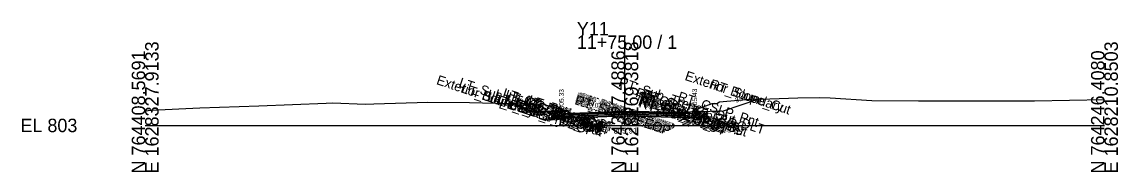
# Model space of a CAD drawing. Extents: x -26 to 203, y -10 to 6017.
# Drawn here: x -25.7 to 202.8, y 3490.3 to 3521.5 of the extents above; entities that cross this region are included whole.
import ezdxf

# ---------------------------------------------------------------- set-up
doc = ezdxf.new("R2010")
doc.units = 0
for name, color, linetype in [('Default', 7, 'Continuous'), ('Exist Cross Section Cell', 7, 'Continuous'), ('Exist XS Center Line Elevation Label', 7, 'Continuous'), ('Exist XS Ground Line', 7, 'Continuous'), ('Prop CMT Conc Surface', 7, 'Continuous'), ('Prop CMT Concrete Structures', 7, 'Continuous'), ('Prop CMT Pvmt Course 1', 7, 'Continuous'), ('Prop CMT Pvmt Course 1 CG', 7, 'Continuous'), ('Prop CMT Pvmt Course 2', 7, 'Continuous'), ('Prop CMT Pvmt Course 3', 7, 'Continuous'), ('Prop CMT Pvmt Surface', 7, 'Continuous'), ('Prop CMT Pvmt Wedge Surface 1', 7, 'Continuous'), ('Prop CMT Pvmt Wedge Surface 2', 7, 'Continuous'), ('Prop CMT Pvmt Wedge Surface 3', 7, 'Continuous'), ('Prop CMT Slope Grass', 7, 'Continuous'), ('Prop CMT Subgrade Earthwork', 7, 'Continuous'), ('Prop XS Hydro Elevations', 7, 'Continuous'), ('Prop XS SE Text', 7, 'Continuous'), ('Prop XS Side Slope Text', 7, 'Continuous'), ('Scratch_Level_0', 7, 'Continuous')]:
    doc.layers.add(name, color=color, linetype=linetype)

msp = doc.modelspace()

# ---------------------------------------------------------------- linework, layer by layer
at = {"layer": 'Exist Cross Section Cell'}
for p, q in [((100, 3500), (100, 3518.72)), ((0, 3500), (100, 3500)), ((100, 3500), (200, 3500))]:
    msp.add_line(p, q, dxfattribs=at)
at = {"layer": 'Exist XS Ground Line'}
msp.add_lwpolyline([(0, 3503.06), (1.23, 3503.14), (11.4, 3503.68), (23.67, 3504.09), (37.71, 3504.6), (39.1, 3504.68), (45.87, 3504.44), (47.66, 3504.48), (58.95, 3504.83), (67.61, 3504.8), (78.51, 3504.48), (83.4, 3504.26), (85.47, 3503.72), (88.37, 3502.79), (88.37, 3502.68), (90.16, 3502.39), (92.43, 3502.55), (98.35, 3502.96), (100, 3502.95), (105, 3502.92), (112.63, 3502.66), (113.63, 3502.81), (114.35, 3502.99), (114.81, 3503.34), (118.22, 3504.55), (119.19, 3504.56), (119.77, 3504.91), (126.73, 3505.52), (128.94, 3505.49), (130.21, 3505.53), (136.06, 3505.75), (140.58, 3505.84), (142.78, 3505.77), (151.53, 3505.18), (161.2, 3505.14), (175.28, 3505.11), (185.4, 3505.11), (200, 3505.41)], dxfattribs=at)
at = {"layer": 'Prop CMT Conc Surface'}
for points in [[(86.78, 3502.33), (86.78, 3502.83), (86.28, 3502.83)], [(88.78, 3502.49), (86.78, 3502.33)], [(112.56, 3502.56), (114.56, 3502.43)], [(114.56, 3502.43), (114.56, 3502.93), (115.06, 3502.93)]]:
    msp.add_lwpolyline(points, dxfattribs=at)
at = {"layer": 'Prop CMT Concrete Structures'}
for points in [[(88.78, 3502.49), (86.78, 3502.33), (86.78, 3502.83), (86.28, 3502.83)], [(86.28, 3502.83), (86.28, 3501.81), (88.78, 3501.9)], [(88.78, 3501.9), (88.78, 3502.49)], [(112.56, 3502.56), (114.56, 3502.43), (114.56, 3502.93), (115.06, 3502.93)], [(115.06, 3502.93), (115.06, 3501.91), (112.56, 3501.98)], [(112.56, 3501.98), (112.56, 3502.56)]]:
    msp.add_lwpolyline(points, dxfattribs=at)
at = {"layer": 'Prop CMT Pvmt Course 1'}
for points in [[(100, 3502.91), (88.78, 3502.49)], [(88.78, 3502.24), (100, 3502.66)], [(88.78, 3502.49), (88.78, 3502.24)], [(100, 3502.66), (100, 3502.91)], [(100, 3502.91), (112.56, 3502.56)], [(100, 3502.66), (100, 3502.91)], [(112.56, 3502.31), (100, 3502.66)], [(112.56, 3502.56), (112.56, 3502.31)]]:
    msp.add_lwpolyline(points, dxfattribs=at)
msp.add_lwpolyline([(100, 3502.66), (100, 3502.78), (100, 3502.78), (100, 3502.66)], close=True, dxfattribs=at)
msp.add_lwpolyline([(100, 3502.66), (100, 3502.78), (100, 3502.78), (100, 3502.66)], close=True, dxfattribs=at)
at = {"layer": 'Prop CMT Pvmt Course 1 CG'}
for points in [[(88.78, 3501.9), (85.78, 3501.79), (85.43, 3501.45)], [(85.43, 3501.45), (88.78, 3501.57)], [(88.78, 3501.57), (88.78, 3501.9)], [(112.56, 3501.98), (115.56, 3501.9), (115.9, 3501.55)], [(112.56, 3501.65), (112.56, 3501.98)], [(115.9, 3501.55), (112.56, 3501.65)]]:
    msp.add_lwpolyline(points, dxfattribs=at)
at = {"layer": 'Prop CMT Pvmt Course 2'}
for points in [[(100, 3502.66), (88.78, 3502.24)], [(88.78, 3501.9), (100, 3502.33)], [(88.78, 3502.24), (88.78, 3501.9)], [(100, 3502.33), (100, 3502.66)], [(100, 3502.33), (100, 3502.66)], [(100, 3502.66), (112.56, 3502.31)], [(100, 3502.66), (100, 3502.66)], [(100, 3502.66), (100, 3502.66)], [(112.56, 3501.98), (100, 3502.33)], [(112.56, 3502.31), (112.56, 3501.98)]]:
    msp.add_lwpolyline(points, dxfattribs=at)
msp.add_lwpolyline([(100, 3502.66), (100, 3502.33), (100, 3502.33)], close=True, dxfattribs=at)
msp.add_lwpolyline([(100, 3502.66), (100, 3502.33), (100, 3502.33)], close=True, dxfattribs=at)
at = {"layer": 'Prop CMT Pvmt Course 3'}
for points in [[(100, 3502.33), (88.78, 3501.9)], [(88.78, 3501.57), (100, 3501.99)], [(88.78, 3501.9), (88.78, 3501.57)], [(100, 3501.99), (100, 3502.33)], [(100, 3502.33), (112.56, 3501.98)], [(100, 3501.99), (100, 3502.33)], [(100, 3502.33), (100, 3502.33), (100, 3501.99), (100, 3501.99)], [(100, 3501.99), (100, 3502.33)], [(100, 3502.33), (100, 3502.33), (100, 3501.99), (100, 3501.99)], [(100, 3501.99), (100, 3502.33)], [(112.56, 3501.65), (100, 3501.99)], [(112.56, 3501.98), (112.56, 3501.65)]]:
    msp.add_lwpolyline(points, dxfattribs=at)
at = {"layer": 'Prop CMT Pvmt Surface'}
for points in [[(100, 3502.91), (88.78, 3502.49)], [(100, 3502.91), (112.56, 3502.56)]]:
    msp.add_lwpolyline(points, dxfattribs=at)
at = {"layer": 'Prop CMT Pvmt Wedge Surface 1'}
for points in [[(100, 3502.91), (100, 3502.66), (100, 3502.66)], [(100, 3502.91), (100, 3502.66), (100, 3502.66)], [(100, 3502.66), (100, 3502.78)], [(100, 3502.66), (100, 3502.78)]]:
    msp.add_lwpolyline(points, dxfattribs=at)
at = {"layer": 'Prop CMT Pvmt Wedge Surface 2'}
for points in [[(100, 3502.91), (100, 3502.66)], [(100, 3502.91), (100, 3502.66)], [(100, 3502.66), (100, 3502.66)], [(100, 3502.66), (100, 3502.66)]]:
    msp.add_lwpolyline(points, dxfattribs=at)
at = {"layer": 'Prop CMT Pvmt Wedge Surface 3'}
for points in [[(100, 3502.91), (100, 3502.33)], [(100, 3502.91), (100, 3502.33)], [(100, 3502.33), (100, 3502.33)], [(100, 3502.33), (100, 3502.33)]]:
    msp.add_lwpolyline(points, dxfattribs=at)
at = {"layer": 'Prop CMT Slope Grass'}
for points in [[(86.28, 3502.83), (80.78, 3502.94), (75.93, 3504.56)], [(115.06, 3502.93), (120.56, 3503.04), (127.95, 3505.5)]]:
    msp.add_lwpolyline(points, dxfattribs=at)
at = {"layer": 'Prop CMT Subgrade Earthwork'}
for points in [[(88.78, 3501.57), (85.43, 3501.45), (84, 3502.88)], [(100, 3501.99), (88.78, 3501.57)], [(100, 3501.99), (112.56, 3501.65)], [(112.56, 3501.65), (115.9, 3501.55), (117.32, 3502.97)]]:
    msp.add_lwpolyline(points, dxfattribs=at)

# ---------------------------------------------------------------- texts
at = {"layer": 'Default'}
msp.add_text('-', height=0.0001, dxfattribs=at).set_placement((0, 3500))
at = {"layer": 'Exist Cross Section Cell'}
for s, p in [('Y11', (90, 3518.72)), ('11+75.00 / 1', (90, 3515.92)), ('EL 803', (-26, 3498.6))]:
    msp.add_text(s, height=2.8, dxfattribs=at).set_placement(p)
for s, p in [('E 1628327.9133', (2.8, 3490)), ('E 1628269.3818', (102.8, 3490)), ('E 1628210.8503', (202.8, 3490)), ('N 764408.5691', (0, 3490)), ('N 764327.4886', (100, 3490)), ('N 764246.4080', (200, 3490))]:
    msp.add_text(s, height=2.8, rotation=90, dxfattribs=at).set_placement(p)
at = {"layer": 'Exist XS Center Line Elevation Label'}
msp.add_text('805.91', height=1.2, dxfattribs=at).set_placement((97.68, 3498.31))
at = {"layer": 'Prop XS Hydro Elevations'}
for s, p in [('805.33', (87.28, 3503.33)), ('805.43', (115.06, 3503.43))]:
    msp.add_text(s, height=1, rotation=90, dxfattribs=at).set_placement(p)
at = {"layer": 'Prop XS SE Text'}
for s, rotation, p in [('0.037', 2.1459, (92.6, 3503.63)), ('0.027', 358.4257, (104.55, 3503.78))]:
    msp.add_text(s, height=1, rotation=rotation, dxfattribs=at).set_placement(p)
at = {"layer": 'Prop XS Side Slope Text'}
for rotation, p in [(18.4332, (123.16, 3504.7)), (341.5668, (77.84, 3504.71))]:
    msp.add_text('3:1', height=1, rotation=rotation, dxfattribs=at).set_placement(p)
at = {"layer": 'Scratch_Level_0'}
for s, p in [('Exterior Boundary', (60.57, 3508.62)), ('Exterior Boundary', (112.38, 3509.5)), ('LT_Sub_Trench_Out_DLT', (65.25, 3508.08)), ('LT_Slope_Cut', (65.78, 3506.89)), ('RT_Sub_Trench_Out_DLT', (98.53, 3508.19)), ('RT_Slope_Cut', (117.55, 3507.78)), ('LT_CSLP_Pnt', (71.14, 3505.1)), ('LT_CG1_Shelf_Out', (72.7, 3505.1)), ('LT_CG_Top_Face', (74.37, 3505.91)), ('LT_CG_Top_BOC', (74.85, 3505.59)), ('LT_CG_Bot_BOC', (74.88, 3504.56)), ('LT_CG_Top_Gut', (75.3, 3505.1)), ('LT_CG_Bot_IE', (78.89, 3504.15)), ('LT_PV2_OEOT', (79.14, 3504.4)), ('LT_PV3_OEOT', (79.14, 3504.06)), ('LT_PV1_OEOT', (79.68, 3504.47)), ('RT_Sub_OEEOP', (89.41, 3504.47)), ('LT_Sub_OEEOP', (89.45, 3504.45)), ('RT_PV2_OEEOP', (89.49, 3505.11)), ('RT_PV3_OEEOP', (89.49, 3504.77)), ('LT_PV2_OEEOP', (89.54, 3505.09)), ('LT_PV3_OEEOP', (89.54, 3504.76)), ('RT_Sub_IEEOP', (90.02, 3504.27)), ('RT_PV1_OEEOP', (90.03, 3505.05)), ('LT_Sub_IEEOP', (90.06, 3504.25)), ('LT_PV1_OEEOP', (90.08, 3505.04)), ('RT_PV2_IEEOP', (90.11, 3504.9)), ('RT_PV3_IEEOP', (90.11, 3504.57)), ('LT_PV2_IEEOP', (90.15, 3504.89)), ('LT_PV3_IEEOP', (90.15, 3504.55)), ('RT_PV1_IEEOP', (90.65, 3504.85)), ('LT_PV1_IEEOP', (90.69, 3504.83)), ('RT_CG_Top_Face', (102.11, 3506.02)), ('RT_CG1_Shelf_Out', (102.44, 3505.22)), ('RT_CG_Bot_IE', (102.63, 3504.24)), ('RT_PV2_OEOT', (102.88, 3504.49)), ('RT_PV3_OEOT', (102.88, 3504.15)), ('RT_CG_Top_Gut', (103.04, 3505.21)), ('RT_PV1_OEOT', (103.42, 3504.56)), ('RT_CG_Top_BOC', (103.59, 3505.7)), ('RT_CG_Bot_BOC', (103.61, 3504.67)), ('RT_CSLP_Pnt', (110.88, 3505.21)), ('LT_Sub_OEOP', (75.73, 3503.62)), ('LT_Sub_OEOT', (79.05, 3503.76)), ('Sub_PGL', (93.81, 3503)), ('PV2_PGL', (93.9, 3503.64)), ('PV3_PGL', (93.9, 3503.3)), ('PV1_PGL', (94.44, 3503.71)), ('RT_Sub_OEOT', (102.79, 3503.85)), ('RT_Sub_OEOP', (106.16, 3503.75))]:
    msp.add_text(s, height=2, rotation=341.5651, dxfattribs=at).set_placement(p)

doc.saveas('drawing.dxf')
